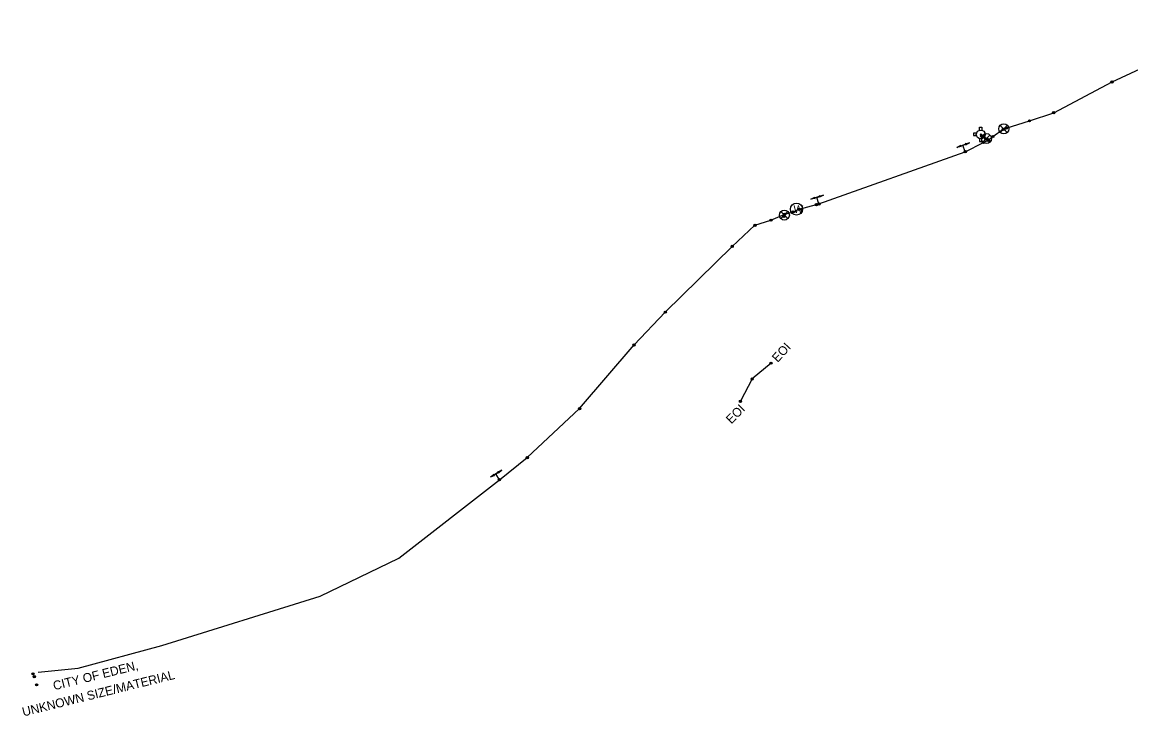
# Model space of a CAD drawing. Extents: x 1768538 to 1769517, y 999883 to 1000769.
# Drawn here: x 1768538.4 to 1769035.2, y 999883 to 1000193.7 of the extents above; entities that cross this region are included whole.
import ezdxf

# ---------------------------------------------------------------- set-up
doc = ezdxf.new("R2010")
doc.units = 0
for name, color, linetype in [('CTL North Arrow NAD 83 2001 CELL', 7, 'Continuous'), ('CTL Primary Horizontal and Vertical CELL', 7, 'Continuous'), ('Default', 7, 'Continuous'), ('Default Symbol CELL', 7, 'Continuous'), ('Exist Property Owner Number CELL', 7, 'Continuous'), ('Exist Utilities Sanitary Sewer Manhole CELL', 7, 'Continuous'), ('Exist Utilities Water Text', 7, 'Continuous'), ('HB-0035 location', 7, 'Continuous'), ('PH Exist DTM Breakline', 7, 'Continuous'), ('Scratch_Level_4', 7, 'Continuous')]:
    doc.layers.add(name, color=color, linetype=linetype)

# ---------------------------------------------------------------- blocks, each defined once
blk = doc.blocks.new('SurveyPointCell')
at = {"layer": 'Default'}
for p, q in [((-0.5, 0), (0.5, 0)), ((0, -0.5), (0, 0.5))]:
    blk.add_line(p, q, dxfattribs=at)
blk.add_circle((0, 0), 0.5, dxfattribs=at)

msp = doc.modelspace()

# ---------------------------------------------------------------- linework, layer by layer
at = {"layer": 'CTL North Arrow NAD 83 2001 CELL'}
for p, q in [((1768962.9, 1000139.69), (1768957.31, 1000137.61)), ((1768959.96, 1000138.6), (1768962.9, 1000139.69)), ((1768961.04, 1000135.7), (1768959.96, 1000138.6)), ((1768961.04, 1000135.7), (1768961.04, 1000135.7)), ((1768897.52, 1000116.19), (1768891.85, 1000114.36)), ((1768894.54, 1000115.23), (1768897.52, 1000116.19)), ((1768895.49, 1000112.29), (1768894.54, 1000115.23)), ((1768895.49, 1000112.29), (1768895.49, 1000112.29)), ((1768753.33, 999992.97), (1768748.26, 999989.83)), ((1768750.66, 999991.31), (1768753.33, 999992.97)), ((1768752.29, 999988.69), (1768750.66, 999991.31)), ((1768752.29, 999988.69), (1768752.29, 999988.69))]:
    msp.add_line(p, q, dxfattribs=at)
for points in [[(1768957.31, 1000137.61), (1768959.04, 1000138.62), (1768958.76, 1000138.15), (1768959.23, 1000138)], [(1768962.9, 1000139.69), (1768961.17, 1000138.68), (1768961.44, 1000139.15), (1768960.98, 1000139.3)], [(1768891.85, 1000114.36), (1768893.62, 1000115.29), (1768893.33, 1000114.84), (1768893.78, 1000114.66)], [(1768897.52, 1000116.19), (1768895.76, 1000115.26), (1768896.05, 1000115.72), (1768895.59, 1000115.89)], [(1768748.26, 999989.83), (1768749.75, 999991.16), (1768749.58, 999990.64), (1768750.06, 999990.58)], [(1768753.33, 999992.97), (1768751.83, 999991.64), (1768752.01, 999992.15), (1768751.52, 999992.21)]]:
    msp.add_lwpolyline(points, close=True, dxfattribs=at)
for centre in [(1768961.04, 1000135.7), (1768895.49, 1000112.29), (1768752.29, 999988.69)]:
    msp.add_circle(centre, 0.517, dxfattribs=at)
at = {"layer": 'CTL Primary Horizontal and Vertical CELL'}
msp.add_line((1768885.43, 1000109.98), (1768885.43, 1000109.98), dxfattribs=at)
msp.add_circle((1768885.43, 1000109.98), 2.69, dxfattribs=at)
at = {"layer": 'Exist Property Owner Number CELL'}
for points in [[(1768961.04, 1000135.7), (1768969.18, 1000139.87), (1768971.35, 1000140.81), (1768973.43, 1000142.53), (1768978.1, 1000145.76), (1768979.43, 1000146.23), (1768989.82, 1000149.51), (1769000.69, 1000153.15), (1769026.85, 1000166.94), (1769043.64, 1000174.71), (1769060.72, 1000180.57), (1769071.68, 1000183.46), (1769084.16, 1000186.77), (1769091.58, 1000191.19), (1769094.55, 1000193.73)], [(1768971.15, 1000141.07), (1768970.48, 1000141.43), (1768970.16, 1000141.47), (1768969.1, 1000142.6), (1768968.43, 1000142.73)], [(1768752.29, 999988.67), (1768764.76, 999998.63), (1768788.26, 1000020.59), (1768812.62, 1000049.14), (1768826.64, 1000063.82), (1768856.62, 1000093.25), (1768866.8, 1000102.71), (1768873.99, 1000105.01), (1768880.15, 1000107.7), (1768883.97, 1000108.76), (1768886.66, 1000109.9), (1768894.33, 1000112.01), (1768895.49, 1000112.29)]]:
    msp.add_lwpolyline(points, dxfattribs=at)
at = {"layer": 'Exist Utilities Sanitary Sewer Manhole CELL'}
msp.add_line((1768895.49, 1000112.29), (1768961.04, 1000135.7), dxfattribs=at)
msp.add_lwpolyline([(1768545.59, 999902.47), (1768563.54, 999904.28), (1768600.96, 999914.47), (1768671.98, 999936.59), (1768707.26, 999953.53), (1768752.29, 999988.69)], dxfattribs=at)
at = {"layer": 'HB-0035 location'}
for points in [[(1768979.88, 1000147.51), (1768976.73, 1000144.36), (1768978.3, 1000145.94), (1768979.88, 1000144.36), (1768976.73, 1000147.51)], [(1768972.11, 1000143.16), (1768968.96, 1000140.01), (1768970.54, 1000141.59), (1768972.11, 1000140.01), (1768968.96, 1000143.16)], [(1768881.57, 1000108.86), (1768878.43, 1000105.72), (1768880, 1000107.29), (1768881.57, 1000105.72), (1768878.43, 1000108.86)]]:
    msp.add_lwpolyline(points, dxfattribs=at)
for centre in [(1768978.3, 1000145.94), (1768970.54, 1000141.59), (1768880, 1000107.29)]:
    msp.add_circle(centre, 2.23, dxfattribs=at)
at = {"layer": 'PH Exist DTM Breakline'}
msp.add_line((1768967.99, 1000143.44), (1768967.99, 1000143.44), dxfattribs=at)
for points in [[(1768967.48, 1000145.35), (1768967.48, 1000146.64), (1768968.5, 1000146.64), (1768968.5, 1000145.33)], [(1768966.08, 1000143.95), (1768964.79, 1000143.95), (1768964.79, 1000142.93), (1768966.08, 1000142.93)], [(1768967.48, 1000141.53), (1768967.48, 1000140.24), (1768968.5, 1000140.24), (1768968.5, 1000141.55)]]:
    msp.add_lwpolyline(points, dxfattribs=at)
for radius in [1.98, 0.243]:
    msp.add_circle((1768967.99, 1000143.44), radius, dxfattribs=at)
at = {"layer": 'Scratch_Level_4'}
msp.add_lwpolyline([(1768874.03, 1000040.94), (1768865.55, 1000033.91), (1768860.31, 1000023.9)], dxfattribs=at)

# ---------------------------------------------------------------- block references
at = {"layer": 'Default'}
for p in [(1769026.85, 1000166.94), (1768989.82, 1000149.51), (1769000.69, 1000153.15), (1768978.1, 1000145.76), (1768979.43, 1000146.23), (1768968.43, 1000142.73), (1768969.1, 1000142.6), (1768969.18, 1000139.87), (1768970.16, 1000141.47), (1768970.48, 1000141.43), (1768971.15, 1000141.07), (1768971.35, 1000140.81), (1768973.43, 1000142.53), (1768961.04, 1000135.7), (1768886.66, 1000109.9), (1768894.33, 1000112.01), (1768895.49, 1000112.29), (1768873.99, 1000105.01), (1768879.79, 1000106.78), (1768880.15, 1000107.7), (1768883.97, 1000108.76), (1768866.8, 1000102.71), (1768856.62, 1000093.25), (1768826.64, 1000063.82), (1768812.62, 1000049.14), (1768874.03, 1000040.94), (1768865.55, 1000033.91), (1768788.26, 1000020.59), (1768860.31, 1000023.9), (1768764.76, 999998.63), (1768752.29, 999988.67), (1768543.26, 999901.78), (1768543.86, 999900.51), (1768544.89, 999896.85)]:
    msp.add_blockref('SurveyPointCell', p, dxfattribs=at)

# ---------------------------------------------------------------- texts
at = {"layer": 'CTL Primary Horizontal and Vertical CELL'}
msp.add_text('W', height=3.5, dxfattribs=at).set_placement((1768884.08, 1000108.23))
at = {"layer": 'Default Symbol CELL'}
for rotation, p in [(47.3733, (1768876.98, 1000041.04)), (45.5005, (1768856.23, 1000013.49))]:
    msp.add_text('EOI', height=4.02, rotation=rotation, dxfattribs=at).set_placement(p)
at = {"layer": 'Exist Utilities Water Text'}
for s, p in [('CITY OF EDEN,', (1768552.81, 999894.36)), ('UNKNOWN SIZE/MATERIAL', (1768539, 999882.65))]:
    msp.add_text(s, height=4.02, rotation=13.9207, dxfattribs=at).set_placement(p)

doc.saveas('drawing.dxf')
